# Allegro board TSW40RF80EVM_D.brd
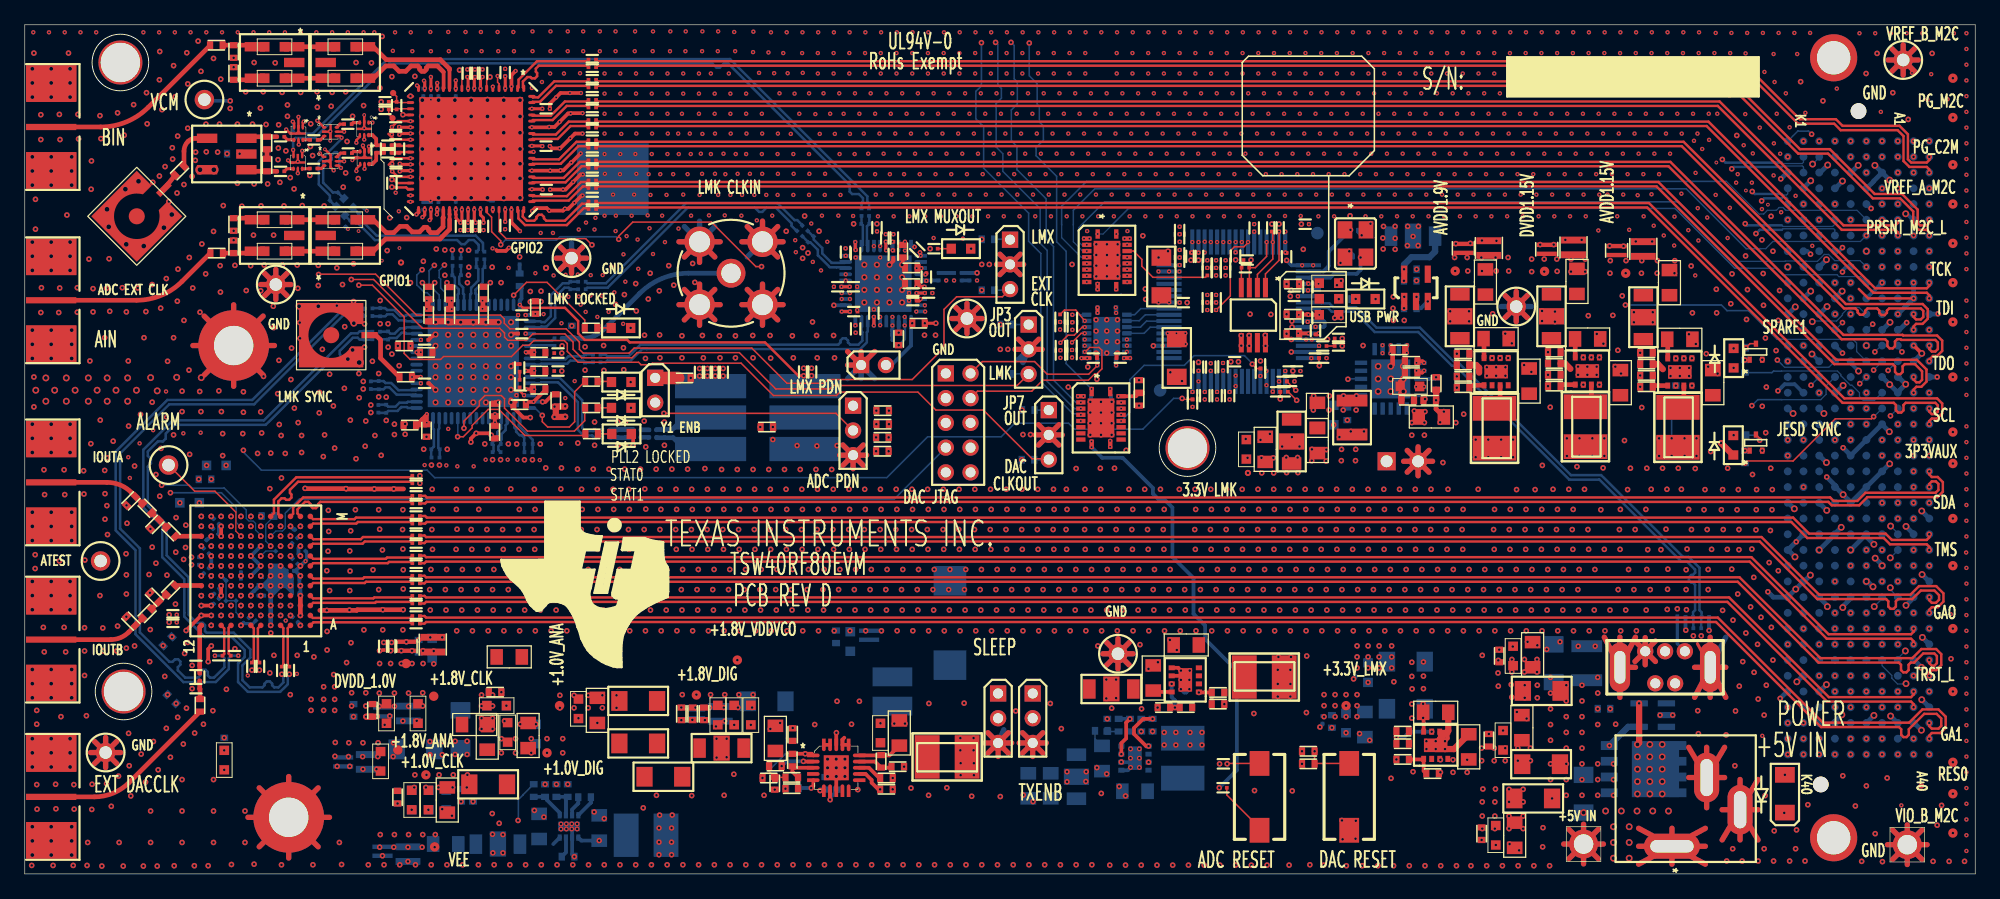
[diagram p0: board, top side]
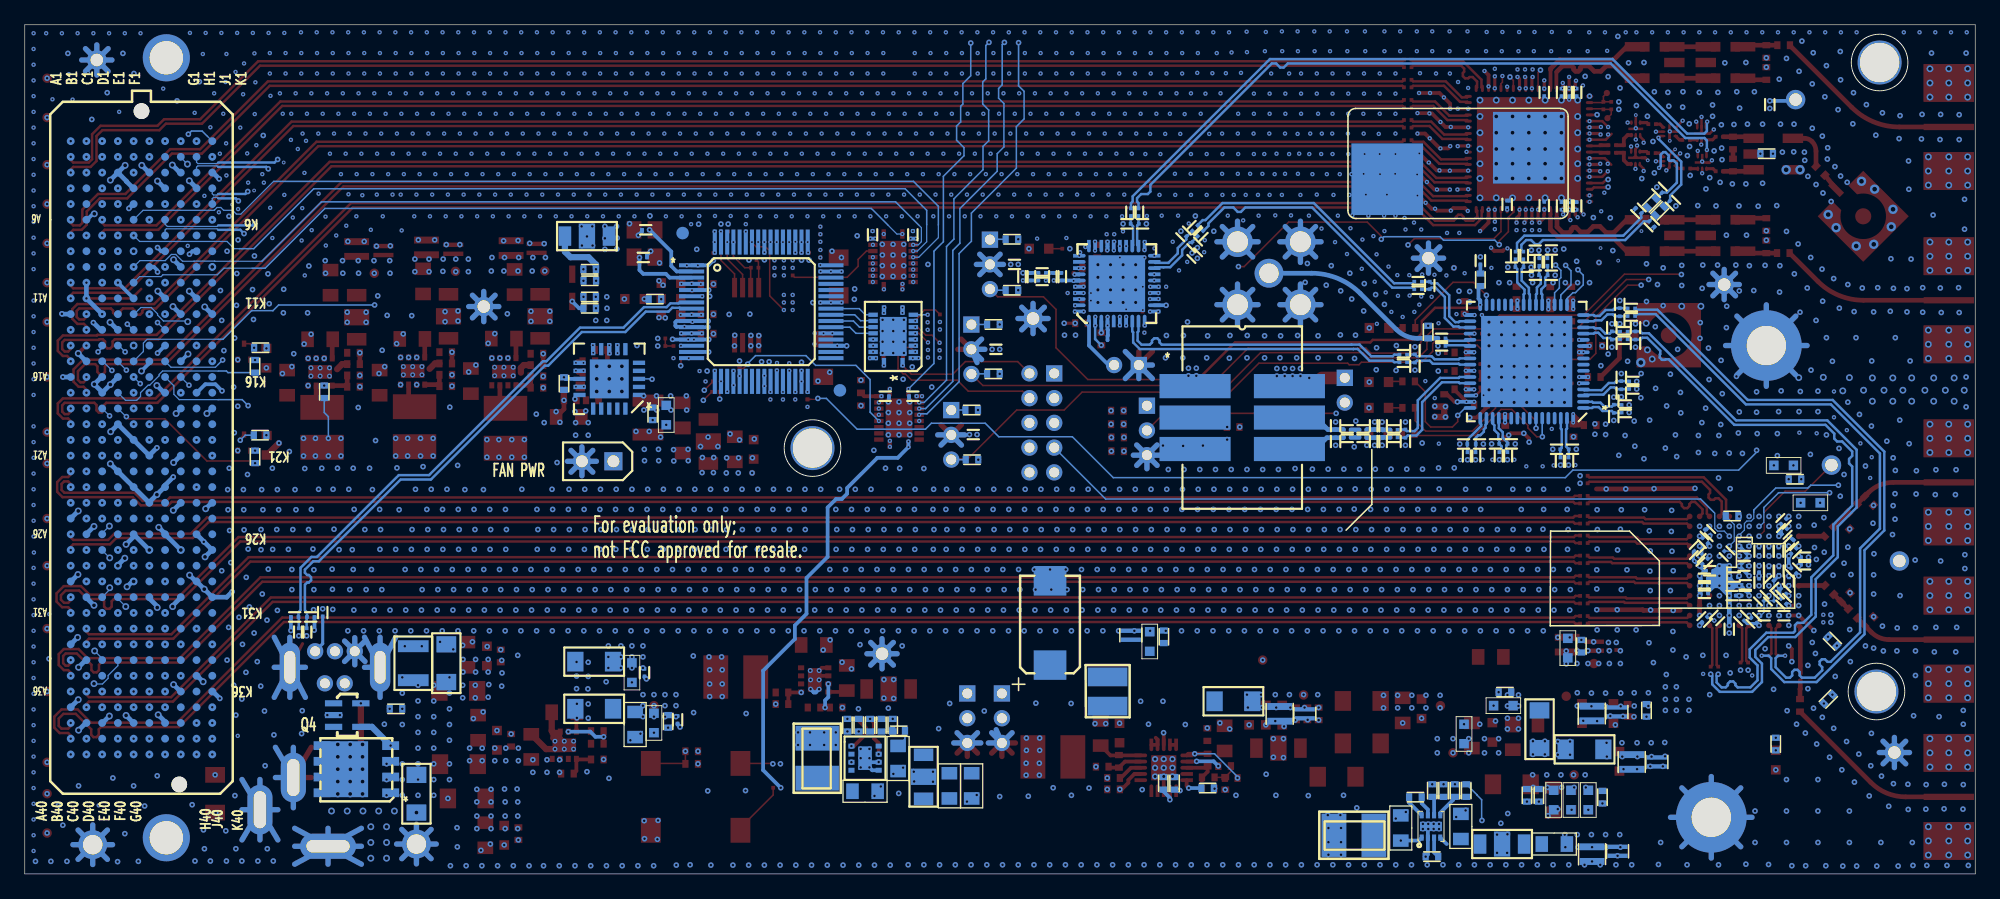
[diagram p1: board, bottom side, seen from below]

Outline 157.48 x 68.58 mm; copper layers: TOP, L2_GND, L3_PWR_SIG, L4_SIG, L5_GND, L6_SIG, L7_GND, L8_SIG, L9_GND, L10_PWR_SIG, L11_GND, BOTTOM. Coordinates in mm from the lower left corner of the outline.
Outline path: 0,68.58 0,0 157.48,0 157.48,68.58 0,68.58

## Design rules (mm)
net group ADC_SYNC: nets ADC_SYNC_N ADC_SYNC_P
net group ADC_SYSREF: nets ADC_SYSREFN ADC_SYSREFP
net group CAR_SYSREF: nets CAR_SYSREFM CAR_SYSREFP
net group CLK_LAO: nets CLK_LAO_0M CLK_LAO_0P
net group CLKIN0: nets CLKIN0_N CLKIN0_P
net group DA0: nets DA0N DA0P
net group DAC_ALT_SYNC: nets DAC_ALT_SYNC_N DAC_ALT_SYNC_P
net group DAC_CLK: nets LMK_DAC_CLKN LMK_DAC_CLKP
net group DAC_CLKOUT: nets DAC_CLKOUTN DAC_CLKOUTP
net group DAC_SYNC: nets DAC_SYNC_N DAC_SYNC_P
net group DCLKOUT2: nets DCLKOUT2N DCLKOUT2P
net group DCLKOUT4: nets DCLKOUT4N DCLKOUT4P
net group DIFFPAIR9: nets GTXCLKM GTXCLKP
net group DIFFPAIR12: nets FPGA_CLK1N FPGA_CLK1P
net group DIFFPAIR13: nets FPGA_CLK1_N FPGA_CLK1_P
net group DIFFPAIR14: nets FPGA_CLK2N FPGA_CLK2P
net group DIFFPAIR15: nets FPGA_CLK2_N FPGA_CLK2_P
net group DP0_C2M: nets DP0_C2M_N DP0_C2M_P
net group DP1: nets DM DP
net group DP1_C2M: nets DP1_C2M_N DP1_C2M_P
net group DP2: nets CLKLA_0M CLKLA_0P
net group DP2_C2M: nets DP2_C2M_N DP2_C2M_P
net group DP2_M2C: nets DB2N DB2P
net group DP3: nets CAR_SYSREF_M CAR_SYSREF_P
net group DP3_C2M: nets DP3_C2M_N DP3_C2M_P
net group DP3_M2C: nets DB0N DB0P
net group DP4: nets DACCLK_N DACCLK_P
net group DP4_C2M: nets DP4_C2M_N DP4_C2M_P
net group DP4_M2C: nets DA1N DA1P
net group DP5: nets N20165749 N20165751
net group DP5_C2M: nets DP5_C2M_N DP5_C2M_P
net group DP5_M2C: nets DA3N DA3P
net group DP6_C2M: nets DP6_C2M_N DP6_C2M_P
net group DP6_M2C: nets DA2N DA2P
net group DP7: nets OSCI OSCO
net group DP7_C2M: nets DP7_C2M_N DP7_C2M_P
net group DP8: nets AINM AINP
net group DP8_M2C: nets DB1N DB1P
net group DP9: nets BINM BINP
net group DP9_M2C: nets DB3N DB3P
net group DP10: nets ADC_CLKINM ADC_CLKINP
net group DP11: nets TXA0_M TXA0_P
net group DP12: nets TXA1_M TXA1_P
net group DP13: nets TXA2_M TXA2_P
net group DP14: nets TXA3_M TXA3_P
net group DP15: nets TXB0_M TXB0_P
net group DP16: nets TXB1_M TXB1_P
net group DP17: nets TXB2_M TXB2_P
net group DP18: nets TXB3_M TXB3_P
net group DP19: nets LMX_OSCM LMX_OSCP
net group DP20: nets CLKIN1N CLKIN1P
net group DP21: nets N20076866 N20076868
net group GTX_CLK: nets GTX_CLKM GTX_CLKP
net group LMK_ADC_CLK: nets LMK_ADC_CLKN LMK_ADC_CLKP
net group LMK_DAC_SYSREF: nets LMK_DAC_SYSREFN LMK_DAC_SYSREFP
net group LMX_CLKA: nets LMX_CLKAN LMX_CLKAP
net group LMX_CLKB: nets LMX_CLKBN LMX_CLKBP
net group OSCIN: nets OSCINN OSCINP
net group OSCOUT: nets OSCOUTN OSCOUTP
net group RX0: nets RX0N RX0P
net group RX1: nets RX1N RX1P
net group RX2: nets RX2N RX2P
net group RX3: nets RX3N RX3P
net group RX4: nets RX4N RX4P
net group RX5: nets RX5N RX5P
net group RX6: nets RX6N RX6P
net group RX7: nets RX7N RX7P
net group SDCLKOUT3: nets SDCLKOUT3N SDCLKOUT3P
net group SDCLKOUT5: nets SDCLKOUT5N SDCLKOUT5P
net group SYSREF-: nets SYSREF-N SYSREF-P
net group USB_M: nets USB_DM USB_DP
net group Y2: nets Y2_N Y2_P

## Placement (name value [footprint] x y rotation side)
C1  0.01uF  [0402]  14.15 13.61 90 top
C7  .1uF  [0201]  18.34 16.76 270 top
C9  .1uF  [0201]  18.95 16.76 270 top
C10  .1uF  [0201]  31.6 20.83 180 top
C11  .1uF  [0201]  31.6 20.22 180 top
C12  .1uF  [0201]  31.6 21.84 180 top
C13  .1uF  [0201]  31.6 22.45 180 top
C14  .1uF  [0201]  31.6 23.47 180 top
C15  .1uF  [0201]  31.6 24.08 180 top
C16  .1uF  [0201]  31.6 25.7 180 top
C17  .1uF  [0201]  31.6 25.1 180 top
C18  .1uF  [0201]  31.6 31.55 180 top
C19  .1uF  [0201]  31.6 32.16 180 top
C20  .1uF  [0201]  31.6 29.92 180 top
C21  .1uF  [0201]  31.6 28.91 180 top
C22  .1uF  [0201]  31.6 30.53 180 top
C23  .1uF  [0201]  31.6 28.3 180 top
C24  .1uF  [0201]  31.6 27.33 180 top
C25  .1uF  [0201]  31.6 26.72 180 top
C26  5600pF  [0402]  11.81 27.63 135 top
C27  5600pF  [0402]  11.79 22.94 225 top
C28  .001uF  [0402]  103.63 9.91 180 top
C29  .1uF  [0201]  11.96 20.32 180 top
C30  10uF  [0603]  32.89 18.24 90 bottom
C31  1uF  [0402]  31.8 18.39 270 bottom
C32  .1uF  [0201]  21.87 23.27 0 bottom
C33  .1uF  [0201]  19.46 23.98 180 bottom
C34  .1uF  [0201]  19.63 22.48 180 bottom
C35  .1uF  [0201]  18.57 23.34 180 bottom
C36  .1uF  [0201]  19.86 19.76 270 bottom
C37  .1uF  [0201]  29.62 18.39 90 top
C38  .1uF  [0201]  21.44 24.49 0 bottom
C39  .1uF  [0201]  21.87 23.88 0 bottom
C40  .1uF  [0201]  18.57 22.48 0 bottom
C41  .1uF  [0201]  21.87 22.66 0 bottom
C42  .1uF  [0201]  28.98 18.39 90 top
C43  10uF  [0603]  41.27 11.3 90 bottom
C44  1uF  [0201]  18.67 24.87 0 bottom
C45  .1uF  [0201]  18.67 25.68 0 bottom
C46  .1uF  [0201]  18.64 26.47 180 bottom
C47  10uF  [0603]  38.1 13.59 0 top
C48  1uF  [0402]  37.97 14.68 180 top
C49  .1uF  [0201]  21.79 26.92 45 bottom
C50  .1uF  [0201]  21.82 25.25 315 bottom
C51  10uF  [0603]  31.24 5.97 270 top
C52  1uF  [0402]  35.23 6.35 90 bottom
C53  .1uF  [0201]  16.66 26.06 90 bottom
C54  .1uF  [0201]  16.66 24.46 270 bottom
C55  10uF  [0603]  32.64 5.97 270 bottom
C56  1uF  [0402]  36.2 6.35 90 bottom
C57  .1uF  [0201]  17.27 22.28 225 bottom
C58  .1uF  [0201]  17.45 23.55 90 bottom
C59  10uF  [0603]  38.1 13.59 0 bottom
C60  1uF  [0402]  37.97 14.68 180 bottom
C61  .1uF  [0201]  17.45 26.06 90 bottom
C62  .1uF  [0201]  17.45 24.66 270 bottom
C63  10uF  [0603]  31.24 5.97 270 bottom
C64  1uF  [0402]  30.1 6.2 90 top
C65  .1uF  [0201]  15.88 26.06 90 bottom
C66  .1uF  [0201]  15.85 24.46 270 bottom
C67  10uF  [0603]  15.47 32.99 180 bottom
C68  1uF  [0402]  14.55 31.88 0 bottom
C69  .1uF  [0201]  14.88 26.75 135 bottom
C70  .1uF  [0201]  15.04 23.65 270 bottom
C71  10uF  [0603]  16.1 9.19 270 top
C72  1uF  [0402]  16.1 10.49 270 bottom
C73  .1uF  [0201]  14.66 24.49 225 bottom
C74  .1uF  [0201]  14.66 26.09 135 bottom
C75  10uF  [0603]  28.73 9.09 270 top
C76  1uF  [0402]  11.86 14.12 315 bottom
C77  .1uF  [0201]  13.77 25.58 180 bottom
C78  .1uF  [0201]  13.77 24.97 180 bottom
C79  10uF  [0603]  29.21 12.95 270 top
C80  1uF  [0402]  28.07 13.21 90 top
C81  .1uF  [0201]  15.44 20.85 180 bottom
C82  .1uF  [0201]  17.04 20.85 0 bottom
C83  10uF  [0603]  66.65 18.77 90 bottom
C84  1uF  [0402]  65.51 19.15 270 bottom
C85  .1uF  [0201]  16.46 22.28 225 bottom
C86  .1uF  [0201]  16.48 23.47 135 bottom
C87  1uF  [0402]  30.1 6.2 90 bottom
C88  .1uF  [0201]  18.87 20.68 225 bottom
C89  10uF  [0603]  58.62 12.83 270 top
C90  1uF  [0402]  54.84 12.93 90 top
C91  .1uF  [0201]  21.84 20.55 315 bottom
C92  .1uF  [0201]  20.85 20.68 315 bottom
C93  10uF  [0603]  57.28 12.83 270 top
C94  1uF  [0402]  53.01 12.93 90 top
C95  10uF  [0603]  34.04 5.97 270 bottom
C96  .1uF  [0201]  20.04 25.86 45 bottom
C97  10uF  [0603]  55.96 12.83 270 top
C98  1uF  [0402]  53.92 12.93 90 top
C99  .1uF  [0201]  22.45 25.48 315 bottom
C100  .1uF  [0201]  22.45 26.29 315 bottom
C101  10uF  [0603]  31.75 12.95 270 top
C102  1uF  [0402]  26.54 13.21 90 bottom
C103  .1uF  [0201]  17.88 20.47 225 bottom
C104  10uF  [0603]  13.31 29.97 180 bottom
C105  1uF  [0402]  11.53 18.8 45 bottom
C106  .1uF  [0201]  15.42 27.66 135 bottom
C107  .1uF  [0201]  15.47 28.47 135 bottom
C108  .1uF  [0201]  15.49 22.83 225 bottom
C109  .1uF  [0201]  15.47 22.02 225 bottom
C110  .1uF  [0201]  45.82 58.65 0 top
C111  .1uF  [0201]  45.82 59.26 0 top
C112  .1uF  [0201]  36.4 52.3 270 top
C113  .1uF  [0201]  35.18 52.3 270 top
C114  .1uF  [0201]  34.8 53.98 90 bottom
C115  .1uF  [0201]  33.4 53.95 90 bottom
C116  .1uF  [0201]  32.18 53.95 90 bottom
C117  .1uF  [0201]  29.97 57.35 180 top
C118  .1uF  [0201]  29.95 59.72 180 top
C119  .1uF  [0201]  32.18 63.12 270 bottom
C120  .1uF  [0201]  33.4 63.12 270 bottom
C121  .1uF  [0201]  34.8 63.12 270 bottom
C122  .1uF  [0201]  36.35 64.67 90 top
C123  .1uF  [0201]  45.82 57.02 0 top
C124  .1uF  [0201]  45.82 57.63 0 top
C125  .1uF  [0201]  45.82 55.4 0 top
C126  .1uF  [0201]  45.82 56.01 0 top
C127  .1uF  [0201]  45.82 53.7 0 top
C128  .1uF  [0201]  42.09 61.8 0 top
C129  .1uF  [0201]  42.09 58.78 0 top
C130  .1uF  [0201]  42.11 55.27 0 top
C131  .1uF  [0201]  38.79 52.37 270 top
C132  .1uF  [0201]  37.03 52.3 270 top
C133  .1uF  [0201]  36.96 64.67 90 top
C134  .1uF  [0201]  38.79 64.72 90 top
C135  .1uF  [0201]  45.82 54.31 0 top
C136  .1uF  [0201]  45.82 60.88 0 top
C137  .1uF  [0201]  45.82 60.27 0 top
C138  .1uF  [0201]  45.82 62.51 0 top
C139  .1uF  [0201]  77.57 49.23 0 bottom
C140  .1uF  [0201]  45.82 61.9 0 top
C141  .1uF  [0201]  45.82 64.14 0 top
C142  .1uF  [0201]  35.79 52.3 270 top
C143  .1uF  [0201]  32.79 53.95 90 bottom
C144  .01uF  [0201]  29.97 56.74 180 top
C145  .01uF  [0201]  29.95 60.33 180 top
C146  .1uF  [0201]  32.79 63.12 270 bottom
C147  .1uF  [0201]  35.74 64.67 90 top
C148  .1uF  [0201]  45.82 63.53 0 top
C149  .1uF  [0201]  45.82 65.76 0 top
C150  .1uF  [0201]  45.82 65.15 0 top
C153  .01uF  [0402]  12.5 56.79 45 top
C154  .1uF  [0402]  16.84 58.17 180 bottom
C157  .1uF  [0201]  16.59 62.13 270 bottom
C158  .1uF  [0603]  25.88 52.83 0 top
C159  .1uF  [0402]  16.87 52.45 90 top
C160  .1uF  [0402]  15.49 50.14 0 top
C161  .1uF  [0402]  16.87 50.65 270 top
C162  .1uF  [0603]  25.88 50.29 0 top
C163  .1uF  [0603]  25.88 66.8 0 top
C164  .1uF  [0402]  15.47 66.93 0 top
C165  .1uF  [0402]  16.87 66.42 90 top
C166  .1uF  [0402]  16.87 64.64 270 top
C167  .1uF  [0603]  25.88 64.26 0 top
C168  100pF  [0201]  68.81 52.2 270 top
C170  10pF  [0201]  68.17 53.44 90 bottom
C171  10pF  [0201]  67.56 53.44 90 bottom
C172  .1uF  [0201]  68.55 45.29 90 top
C173  .1uF  [0201]  65.63 47.42 180 top
C174  1uF  [0201]  66.9 47.42 180 top
C176  .1uF  [0201]  66.93 45.42 0 top
C177  .1uF  [0201]  67.08 44.02 90 top
C178  100pF  [0201]  63.02 49.93 225 bottom
C179  .1uF  [0201]  67.08 50.09 270 top
C180  .1uF  [0201]  69.52 51.36 270 top
C181  10pF  [0201]  62.56 51.72 135 bottom
C182  .1uF  [0201]  70.13 50.04 270 top
C183  1uF  [0201]  70.13 51.36 270 top
C184  10pF  [0201]  62.99 52.15 135 bottom
C185  .1uF  [0201]  72.97 46.91 0 top
C186  10uF  [0402]  70.89 50.29 90 top
C187  1uF  [0201]  71.7 46.91 0 top
C188  10uF  [0402]  71.58 47.68 0 top
C189  1uF  [0201]  71.7 46.3 0 top
C190  10uF  [0402]  70.56 43.21 90 top
C191  10uF  [0402]  71.58 48.95 0 top
C192  560pF  [0201]  76.89 48.23 270 bottom
C193  .047uF  [0201]  76.28 48.23 270 bottom
C194  6800pF  [0201]  74.4 48.23 270 bottom
C195  6800pF  [0201]  72.8 48.21 90 top
C196  0.1uF  [0201]  27.76 45.06 180 bottom
C197  0.1uF  [0201]  27.76 45.67 180 bottom
C198  .68uF  [0402]  39.95 47.98 90 bottom
C199  0.1uF  [0201]  28.24 37.26 180 bottom
C200  0.1uF  [0201]  62.89 40.54 90 top
C201  0.1uF  [0201]  28.24 37.87 180 bottom
C202  3900pF  [0201]  39.95 39.6 90 top
C203  47pF  [0201]  40.01 38.66 180 top
C204  0.1uF  [0201]  43.08 43.26 180 bottom
C206  0.1uF  [0201]  43.08 42.65 180 bottom
C207  10pF  [0201]  36.49 49.95 90 bottom
C208  10pF  [0201]  37.11 49.95 90 bottom
C216  0.1uF  [0201]  38.42 33.76 270 bottom
C217  0.1uF  [0201]  37.77 33.76 270 bottom
C218  0.1uF  [0201]  54.48 40.51 270 top
C219  100pF  [0201]  55.12 40.51 270 top
C220  0.1uF  [0201]  49.43 35.86 180 bottom
C221  .1uF  [0201]  46.95 35.86 180 bottom
C222  2200pF  [0201]  55.75 40.51 270 top
C223  0.1uF  [0201]  46.01 36.19 270 bottom
C224  0.1uF  [0201]  40.99 33.75 270 bottom
C225  10pF  [0201]  56.39 40.51 270 top
C226  0.1uF  [0201]  40.34 33.75 270 bottom
C227  0.1uF  [0201]  49.43 35.25 180 bottom
C228  0.1uF  [0201]  46.95 35.25 180 bottom
C229  12pF  [0201]  46.01 34.92 90 bottom
C230  .1uF  [0201]  46.18 41.94 0 bottom
C231  .1uF  [0201]  46.18 41.33 0 bottom
C232  1uF  [0402]  32.41 42.11 180 top
C233  .1uF  [0201]  40.13 45.13 0 top
C234  0.01uF  [0201]  40.13 43.64 0 top
C235  1uF  [0402]  32.61 45.13 90 top
C236  1uF  [0402]  34.32 45.11 90 top
C237  1uF  [0402]  37.03 45.13 90 top
C238  1uF  [0402]  39.95 37.9 0 top
C239  .1uF  [0201]  43.05 40.61 180 top
C240  0.01uF  [0201]  43.05 42.06 180 top
C241  .1uF  [0201]  32.28 43.13 0 top
C242  10uF  [0402]  30.63 42.65 180 top
C243  1uF  [0402]  37.95 37.47 270 top
C244  1uF  [0402]  32.44 35.81 90 top
C245  .1uF  [0201]  94.76 40.93 270 top
C246  .1uF  [0201]  94.16 49.88 90 top
C247  .1uF  [0201]  103.58 44.9 270 top
C248  4.7uF  [0402]  102.38 45.2 180 top
C249  .1uF  [0201]  93.55 46.14 180 top
C250  .1uF  [0201]  101.88 49.85 90 top
C251  .1uF  [0201]  94.76 49.88 90 top
C252  10uF  [0402]  111.87 46.6 0 bottom
C253  .1uF  [0201]  104.21 43.88 270 top
C254  1uF  [0402]  111.86 47.9 0 bottom
C255  .1uF  [0201]  97.76 49.9 90 top
C256  10uF  [0402]  111.87 48.83 0 bottom
C257  .1uF  [0201]  103.6 47.41 270 top
C258  4.7uF  [0402]  102.38 47.64 180 top
C259  100uF  [1206]  91.77 48.25 90 top
C260  .1uF  [0201]  88.01 38.58 0 bottom
C261  .1uF  [0201]  85.78 38.58 0 bottom
C262  10uF  [0402]  102.38 43.63 180 top
C263  100uF  [1206]  93.01 41.67 270 top
C264  .1uF  [0201]  88.45 41.66 180 top
C265  .1uF  [0201]  86.27 41.66 180 top
C266  22pF  [0201]  134.39 20.75 180 bottom
C267  22pF  [0201]  135.69 20.75 0 bottom
C268  .1uF  [0201]  97.69 41.37 0 top
C269  27pF  [0201]  107.34 52.02 0 bottom
C270  27pF  [0201]  107.55 49.79 180 bottom
C273  47uF  [1210]  126.11 17.02 90 bottom
C274  22uF  [1206]  123.44 17.02 270 bottom
C275  10uF  [0805]  120.29 3.12 270 top
C276  1.0uF  [0603]  118.77 3.12 270 top
C277  .1uF  [0402]  117.63 3.25 90 top
C278  10uF  [0508]  30.94 1.6 270 bottom
C279  47uF  [0805]  41.53 3.84 90 bottom
C280  1uF  [0306]  28.88 1.83 270 bottom
C281  10uF  [0805]  46.38 3.71 90 bottom
C282  1uF  [0402]  45.2 6.2 0 bottom
C283  4.7uF  [0402]  43.87 1.4 0 bottom
C285  10uF  [0805]  93.78 18.49 180 top
C288  10uF  [0508]  32.94 18.52 90 top
C289  1uF  [0306]  30.78 18.39 90 top
C290  22uF  [0805]  91.11 15.82 270 top
C294  22uF  [0805]  86.97 9.32 90 bottom
C295  10uF  [0805]  81.03 7.11 270 bottom
C297  10uF  [0508]  30.96 12.95 270 bottom
C298  1uF  [0306]  28.93 13.08 270 bottom
C299  10uF  [0805]  89.64 6.68 180 bottom
C300  10uF  [0508]  56.16 12.93 270 bottom
C301  1uF  [0306]  54.13 12.93 270 bottom
C302  10uF  [0508]  27.74 9.04 270 bottom
C303  1uF  [0306]  25.7 9.04 270 bottom
C308  10uF  [0805]  34.11 5.97 270 top
C309  1.0uF  [0603]  32.59 5.97 270 top
C313  .1uF  [0402]  62 11.25 270 top
C314  10uF  [0805]  40.64 11.18 90 top
C315  47uF  [0805]  60.6 10.95 90 top
C316  1.0uF  [0603]  38.99 11.43 90 top
C317  0.01uF  [0402]  61.98 9.19 90 top
C318  47uF  [0805]  70.61 11.38 90 top
C320  1.0uF  [0603]  69.09 11.38 90 top
C324  10uF  [0805]  46.23 13.21 270 top
C325  1.0uF  [0603]  44.7 13.34 270 top
C326  0.01uF  [0402]  69.57 7.75 180 top
C327  1.0uF  [0402]  69.57 6.83 180 top
C340  10uF  [0805]  113.56 36.91 0 top
C341  .1uF  [0402]  113.44 38.25 180 top
C342  0.01uF  [0402]  111.66 38.25 0 top
C343  .1uF  [0402]  106.78 37.16 270 bottom
C344  1.0uF  [0603]  105.69 37.06 270 bottom
C345  47uF  [1210]  107.16 36.86 270 top
C346  10uF  [0805]  100.15 34.29 90 top
C347  1.0uF  [0603]  98.63 34.29 90 top
C348  1.0uF  [0603]  111.84 39.37 180 top
C353  33uF  [0805]  108.2 12.06 270 bottom
C354  10uF  [0603]  106.68 12.19 270 bottom
C355  .1uF  [0402]  105.54 12.32 270 bottom
C356  .01uF  [0201]  104.78 12.45 270 bottom
C358  10uF  [0603]  108.46 16.26 270 bottom
C359  .01uF  [0201]  107.44 16.26 270 bottom
C360  .1uF  [0201]  15.66 17.62 180 top
C361  .1uF  [0201]  16.94 17.63 0 top
C362  10uF  [0508]  118.21 50.55 90 top
C364  1uF  [0306]  116.15 50.52 90 top
C365  10uF  [0805]  121.46 39.8 90 top
C366  22uF  [0805]  118.8 43.23 180 top
C367  10uF  [0805]  136.3 39.67 90 top
C376  22uF  [0805]  133.63 43.18 180 top
C377  10uF  [0508]  125.04 50.6 90 top
C378  1uF  [0306]  122.89 50.44 90 top
C379  10uF  [0805]  128.83 39.67 90 top
C380  22uF  [0805]  126.19 43.21 180 top
C381  10uF  [0508]  130.68 50.47 90 top
C382  1uF  [0306]  128.52 50.34 90 top
C383  .01uF  [0201]  44.98 47.83 180 bottom
C384  .01uF  [0201]  44.98 47.22 180 bottom
C423  .1uF  [0201]  79.07 42.37 0 bottom
C424  .1uF  [0201]  80.9 35.48 0 bottom
C425  10uF  [0805]  116.59 10.26 90 top
C426  22uF  [0805]  113.92 13.06 180 top
C427  10pF  [0201]  29.31 58.85 0 top
C428  10pF  [0201]  29.31 58.24 0 top
C429  10pF  [0201]  20.65 59.54 0 top
C430  10pF  [0201]  20.65 56.74 0 top
C431  10pF  [0201]  23.34 59.28 0 top
C432  10pF  [0201]  23.32 56.97 0 top
C433  10pF  [0201]  26.09 60.55 0 top
C434  10pF  [0201]  26.11 58.22 0 top
C435  1.0uF  [0603]  120.17 17.6 90 top
C436  .1uF  [0402]  119.05 17.6 270 top
C437  10uF  [0805]  121.74 17.7 90 top
C438  .1uF  [0201]  89.03 51.61 90 bottom
C439  .1uF  [0201]  85.78 51.61 270 bottom
C440  1.0uF  [0603]  119.35 10.79 90 top
C441  .1uF  [0402]  118.21 10.79 270 top
C442  10uF  [0805]  120.88 11.81 90 top
C443  1uF  [0306]  68.17 19.28 90 bottom
C444  470uF  [7343]  74.7 20.27 90 bottom
C445  TBD  [0201]  26.12 52.48 45 bottom
C446  TBD  [0201]  27.19 53.56 225 bottom
C447  TBD  [0201]  24.42 54.17 45 bottom
C448  TBD  [0201]  25.49 55.25 225 bottom
D1  LED GREEN  [LED_0603]  75.59 50.5 0 top
D2  LED GREEN  [LED_0603]  48.16 37.64 0 top
D3  LED GREEN  [LED_0603]  48.18 35.53 0 top
D4  LED GREEN  [LED_0603]  48.13 44.09 0 top
D5  LED GREEN  [LED_0603]  48.16 39.73 0 top
D6  LED GREEN  [LED_0603]  137.95 34.62 90 top
D7  LED GREEN  [LED_0603]  137.97 41.66 90 top
D9  LED GREEN  [LED_0603]  108.24 46.43 0 top
D10  LED GREEN  [LED_1206]  142.11 6.48 270 top
F1  FUSE 2.0A 63V FAST  [1206]  125.86 6.48 90 bottom
FB1  120  [0402]  53.26 40.06 0 top
FB2  120  [0402]  41.22 45.74 270 top
FB3  120  [0402]  34.32 46.89 270 top
FB4  120  [0402]  37.03 46.91 270 top
FB5  120  [0402]  32.61 46.91 270 top
FB6  120  [0402]  42.88 38.23 90 top
FB7  120  [0402]  41.53 42.11 180 top
FB8  120  [0402]  41.53 40.61 180 top
FB9  120  [0402]  41.53 39.14 180 top
FB10  120  [0402]  37.95 35.69 90 top
FB11  120  [0402]  31.09 36.25 0 top
FB12  60 OHM @ 100MHz  [0603]  105.31 45.15 180 top
FB13  27uF  [1206_BEAD_NFM31P]  112.09 51.51 180 bottom
FB14  68 OHM @ 100MHz  [0603]  105.31 47.72 180 top
FB15  68 OHM @ 100MHz  [0603]  105.31 46.45 180 top
FB16  120 @100MHz  [1206]  121.79 6.1 0 top
FB17  27uF  [1206_BEAD_NFM31P]  38.2 2.41 180 bottom
FB18  27uF  [1206_BEAD_NFM31P]  87.73 14.94 180 top
FB20  27uF  [1206_BEAD_NFM31P]  84.91 7.85 270 bottom
FB21  120 OHM @ 100MHz  [1206]  50.11 3.1 180 bottom
FB22  120 OHM @ 100MHz  [1206]  100.1 15.95 180 top
FB23  120 OHM @ 100MHz  [1206]  93.55 9.32 270 bottom
FB24  120 OHM @ 100MHz  [1206]  74.47 9.42 0 top
FB25  120 OHM @ 100MHz  [1206]  118.85 35.99 90 top
FB26  120 OHM @ 100MHz  [1206]  133.53 36.07 90 top
FB27  120 OHM @ 100MHz  [1206]  126.09 36.12 90 top
FB37  27uF  [1206_BEAD_NFM31P]  102.29 34.92 270 top
FB38  120 OHM @ 100MHz  [1206]  111.51 13.34 180 bottom
FB39  120 OHM @ 100MHz  [1206]  111.51 17.14 180 bottom
FB40  27uF  [1206_BEAD_NFM31P]  123.27 45.03 90 top
FB41  27uF  [1206_BEAD_NFM31P]  130.68 44.96 90 top
FB42  27uF  [1206_BEAD_NFM31P]  115.87 45.03 90 top
FB44  120 @100MHz  [1206]  122.48 14.78 0 top
FB45  120 @100MHz  [1206]  122.43 8.86 0 top
FB47  120 OHM @ 100MHz  [1206]  35.18 11.68 90 bottom
FB48  120 OHM @ 100MHz  [1206]  59.89 13.94 180 bottom
FB49  120 OHM @ 100MHz  [1206]  31.55 10.06 180 bottom
FB50  120 OHM @ 100MHz  [1206]  37.41 7.24 180 top
FB51  120 OHM @ 100MHz  [1206]  49.53 10.54 180 top
FB52  120 OHM @ 100MHz  [1206]  49.53 13.97 180 top
FB53  27uF  [1206_BEAD_NFM31P]  56.26 10.16 180 top
HS1  HEAT SINK, DAC38RF8x, RED  [HEATSINK_SVT_10-1003850]  20.04 24.26 0 top
HS2  Copper Heatsink, .7 x .35 with FAN assembly  [HEATSINK_350X700]  41.76 57.38 180 bottom
J1  SMA, JACK, END LAUNCH  [SMA_SMEL_DUAL_PSF-S01_250X215]  0.1 6.22 90 top
J3  SMA, JACK, END LAUNCH  [SMA_SMEL_DUAL_PSF-S01_250X215]  0.1 31.62 90 top
J4  SMA, JACK, END LAUNCH  [SMA_SMEL_DUAL_PSF-S01_250X215]  0.1 18.92 90 top
J5  HDR 2X5  [HDR_THVT_2X5_79_M]  75.36 36.42 0 top
J8  SMP CONN  [SMP_B120]  9.04 53.11 135 top
J9  SMA, JACK, END LAUNCH  [SMA_SMEL_DUAL_PSF-S01_250X215]  0.1 46.33 90 top
J10  SMA, JACK, END LAUNCH  [SMA_SMEL_DUAL_PSF-S01_250X215]  0.1 60.33 90 top
J12  SMA_THVT_REC  [SMA_THVT_312X312]  57.02 48.51 0 top
J13  SMP CONN  [SMP_B120]  24.74 43.51 90 top
J14  CON_SMVT_40x10_SEAM  [CON_SMVT_40X10_SEAM_MTG]  148.06 34.42 90 bottom
J15  MINI B USB 2.0 OTG Receptacle, Vertical  [CON_THVT_USBMINI_AB_F]  132.44 16.69 180 top
J17  PJ-006A  [JACK_THVT_3_520X343X421]  132.99 2.24 270 top
J38  HEADER 2POS, FAN POWER  [HDR_THVT_1X2_100_M]  109.96 33.32 270 bottom
JP1  HDR 1x3 2mm  [HDR_THVT_1X3_79_M]  78.59 12.57 0 top
JP2  HDR 1x3 2mm  [HDR_THVT_1X3_79_M]  81.38 12.57 0 top
JP3  HDR 1x3 2mm  [HDR_THVT_1X3_79_M]  79.55 49.23 0 top
JP4  HDR 1x3 2mm  [HDR_THVT_1X3_79_M]  66.88 35.81 0 top
JP5  HDR 1x2 2mm  [HDR_THVT_1X2_79_M]  68.53 41.1 90 top
JP6  HDR 1x2 2mm  [HDR_THVT_1X2_79_M]  50.9 39.07 0 top
JP7  HDR 1x3 2mm  [HDR_THVT_1X3_79_M]  81.05 42.37 0 top
JP8  HDR 1x3 2mm  [HDR_THVT_1X3_79_M]  82.68 35.46 0 top
L10  1uH  [IND_SM_142X189]  118.67 35.99 90 top
L11  1uH  [IND_SM_142X189]  133.48 36.07 90 top
L12  1uH  [IND_SM_142X189]  126.01 36.12 90 top
L13  1uH  [IND_SM_142X189]  93.5 9.35 270 bottom
L14  1uH  [IND_SM_142X189]  74.47 9.45 0 top
L15  1uH  [IND_SM_142X189]  50.16 3.12 180 bottom
L16  1uH  [IND_SM_142X189]  100.08 15.9 180 top
L17  100uH  [IND_SM_110X138]  70.05 14.71 270 bottom
L18  0 ohm  [0402]  25.48 53.54 135 bottom
L19  0 ohm  [0402]  26.12 54.19 135 bottom
MT1  STANDOFF,  4-40, 3/16 Rd x 1 3/16 Length, ALUM  [MFG125_PLATED]  7.98 14.73 0 top
MT2  STANDOFF,  4-40, 3/16 Rd x 1 3/16 Length, ALUM  [MFG125_PLATED]  7.72 65.53 0 top
MT3  STANDOFF,  4-40, 3/16 Rd x 1 3/16 Length, ALUM  [MFG125_PLATED]  93.88 34.39 0 top
NOREF  -  []  32.87 54.84 0 top
NOREF#2  -  []  116.94 5.84 89.9 top
NOREF#3  -  []  94.92 3.91 0 top
NOREF#4  -  []  32.87 56.74 0 top
NOREF#5  -  []  50.01 79.6 90 top
NOREF#6  -  []  49.38 79.6 90 top
NOREF#7  -  []  91.54 24.26 0 top
NOREF#8  -  []  27.41 33.53 0 top
NOREF#9  -  []  473.3 162.18 0 top
NOREF#10  -  []  35.79 3.94 90 top
NOREF#11  -  []  82.65 4.57 0 top
NOREF#12  -  []  -116.97 325.27 0 top
NOREF#13  -  []  38.58 79.6 90 top
NOREF#14  -  []  395.25 73.96 0 top
NOREF#15  -  []  38.05 60.02 0 top
NOREF#16  -  []  220.98 11.43 0 top
NOREF#17  -  []  5.08 0 90 top
NOREF#18  -  []  58.17 61.11 0 top
NOREF#19  -  []  44.3 58.65 0 top
NOREF#20  -  []  36.64 28.06 0 top
NOREF#21  -  []  59.54 87.86 0 top
NOREF#22  -  []  116.94 5.84 0 top
NOREF#23  -  []  91.54 26.8 0 top
NOREF#24  -  []  -127.66 -149.22 0 top
NOREF#25  -  []  82.65 4.57 90 top
NOREF#26  -  []  48.74 55.47 90 top
NOREF#27  -  []  46.2 52.93 90 top
NOREF#28  -  []  82.65 5.84 0 top
NOREF#29  -  []  67.05 53.22 0 top
NOREF#30  -  []  35.41 52.93 90 top
NOREF#31  -  []  154.69 0.89 0 top
NOREF#32  -  []  91.4 56.79 0 top
NOREF#33  -  []  0 68.58 0 top
NOREF#34  -  []  89.41 -32.49 0 top
NOREF#35  -  []  36.8 12.83 90 top
NOREF#36  -  []  9.02 40.17 0 top
NOREF#37  -  []  105.05 11.23 180 bottom
PP1  PROBE POINT  [PROBE_POINT_30PAD]  33.1 2.18 0 top
PP3  PROBE POINT  [PROBE_POINT_30PAD]  30.78 16.99 0 top
PP5  PROBE POINT  [PROBE_POINT_30PAD]  33.02 14.35 0 top
PP7  PROBE POINT  [PROBE_POINT_30PAD]  54.23 14.45 0 top
PP8  PROBE POINT  [PROBE_POINT_30PAD]  30.12 10.01 0 top
PP11  PROBE POINT  [PROBE_POINT_30PAD]  32.38 8 0 top
PP13  PROBE POINT  [PROBE_POINT_30PAD]  42.16 9.78 0 top
PP15  PROBE POINT  [PROBE_POINT_30PAD]  43.18 13.59 0 top
PP22  PROBE POINT  [PROBE_POINT_22PAD]  98.76 32.38 90 top
PP23  PROBE POINT  [PROBE_POINT_30PAD]  106.68 13.59 0 top
PP27  PROBE POINT  [PROBE_POINT_22PAD]  42.09 48.95 0 top
PP28  PROBE POINT  [PROBE_POINT_22PAD]  30.38 49.38 0 top
PP29  PROBE POINT  [PROBE_POINT_22PAD]  29.74 63.07 0 top
PP30  PROBE POINT  [PROBE_POINT_22PAD]  29.69 61.04 0 top
PP31  PROBE POINT  [PROBE_POINT_30PAD]  115.49 48.69 0 top
PP32  PROBE POINT  [PROBE_POINT_30PAD]  129.26 48.51 0 top
PP33  PROBE POINT  [PROBE_POINT_30PAD]  122.71 48.67 0 top
PP34  PROBE POINT  [PROBE_POINT_30PAD]  155.68 35.69 0 top
PP35  PROBE POINT  [PROBE_POINT_30PAD]  155.68 28.7 0 top
PP36  PROBE POINT  [PROBE_POINT_30PAD]  155.68 19.81 0 top
PP37  PROBE POINT  [PROBE_POINT_30PAD]  155.68 9.02 0 top
PP38  PROBE POINT  [PROBE_POINT_30PAD]  155.68 54.1 0 top
PP39  PROBE POINT  [PROBE_POINT_30PAD]  155.68 64.26 0 top
PP41  PROBE POINT  [PROBE_POINT_30PAD]  155.68 3.3 0 top
PP42  PROBE POINT  [PROBE_POINT_30PAD]  155.68 14.73 0 top
PP43  PROBE POINT  [PROBE_POINT_30PAD]  155.68 44.58 0 top
PP44  PROBE POINT  [PROBE_POINT_30PAD]  155.68 47.75 0 top
PP45  PROBE POINT  [PROBE_POINT_30PAD]  155.68 40.13 0 top
PP46  PROBE POINT  [PROBE_POINT_30PAD]  155.68 24.89 0 top
PP47  PROBE POINT  [PROBE_POINT_30PAD]  155.68 50.93 0 top
PP48  PROBE POINT  [PROBE_POINT_30PAD]  155.68 61.09 0 top
PP49  PROBE POINT  [PROBE_POINT_30PAD]  155.68 57.28 0 top
PP50  PROBE POINT  [PROBE_POINT_30PAD]  155.68 6.48 0 top
PP51  PROBE POINT  [PROBE_POINT_30PAD]  155.68 33.15 0 top
PP52  PROBE POINT  [PROBE_POINT_30PAD]  57.53 17.27 0 top
Q1  DTC114EET1G  [SOT_416_3_63X31]  139.12 34.19 90 top
Q2  DTC114EET1G  [SOT_416_3_63X31]  139.12 41.53 90 top
Q4  CSD18532Q5  [SON_Q5B_8]  130.71 8.46 0 bottom
R1  17.8  [0201]  14.12 15.9 270 top
R2  294  [0201]  13.82 14.96 180 top
R3  294  [0201]  13.82 16.84 180 top
R16  0  [0201]  21.36 16.43 90 top
R17  0  [0201]  20.75 16.43 90 top
R20  0  [0402]  9.88 29.53 315 top
R21  0  [0402]  10.5 28.22 225 top
R22  0  [0402]  8.57 30.13 225 top
R23  0  [0402]  9.87 21.03 45 top
R24  0  [0402]  10.47 22.34 135 top
R25  0  [0402]  8.56 20.42 135 top
R30  1K  [0402]  103.63 8.89 0 top
R31  3.65k  [0201]  11.96 20.93 180 top
R38  10K  [0402]  77.77 51.26 0 bottom
R39  10K  [0402]  77.77 47.14 0 bottom
R45  100  [0201]  29.64 55.78 90 top
R47  1k  [0201]  96.75 6.96 180 top
R49  10k  [0201]  96.77 8.89 0 top
R50  10k  [0201]  37.8 54.08 270 bottom
R51  0  [0201]  29.08 62.36 0 top
R52  100  [0201]  30.02 62.05 90 top
R53  0  [0201]  29.08 61.75 0 top
R54  0  [0603]  20.17 52.83 0 top
R55  0  [0603]  20.17 50.29 0 top
R56  0  [0603]  20.17 66.8 0 top
R57  0  [0603]  20.17 64.26 0 top
R58  49.9  [0201]  68.5 52.5 0 bottom
R59  49.9  [0201]  67.23 52.5 180 bottom
R60  12k  [0402]  72.16 44.48 0 top
R61  49.9  [0201]  63.02 50.8 225 bottom
R62  49.9  [0201]  63.92 51.69 45 bottom
R63  0  [0201]  66.27 50.22 90 top
R64  680  [0201]  73.41 50.5 180 top
R67  680  [0201]  72.06 50.42 135 top
R68  0  [0201]  75.34 48.54 180 bottom
R69  12  [0201]  73.79 48.23 270 bottom
R70  150  [0201]  75.34 47.93 180 bottom
R71  120  [0201]  28.7 44.73 270 bottom
R72  120  [0201]  28.7 46 90 bottom
R73  24.9K  [0201]  63.53 40.54 270 top
R74  100  [0201]  28.37 43.18 180 bottom
R75  100  [0201]  28.37 43.79 180 bottom
R76  39k  [0201]  39.95 49.53 90 bottom
R77  240  [0201]  29.18 38.2 90 bottom
R78  240  [0201]  29.18 36.93 270 bottom
R79  200  [0201]  29.34 42.85 270 bottom
R80  200  [0201]  29.34 44.12 90 bottom
R81  100  [0201]  27.43 42.85 90 bottom
R82  100  [0201]  27.43 44.12 270 bottom
R83  49.9  [0402]  19.56 59.03 270 top
R84  49.9  [0402]  19.56 57.25 270 top
R85  0  [0201]  27.64 39.17 180 bottom
R86  0  [0201]  27.64 39.78 180 bottom
R87  620  [0201]  39.95 40.87 90 top
R89  240  [0201]  28.57 40.11 90 bottom
R90  240  [0201]  28.57 38.84 270 bottom
R93  49.9  [0402]  44.17 43.76 90 bottom
R94  120  [0201]  36.16 49 180 bottom
R95  120  [0201]  37.43 49 0 bottom
R96  0  [0201]  34.54 49.42 90 bottom
R99  0  [0201]  35.19 49.42 90 bottom
R100  200  [0201]  34.22 48.35 180 bottom
R101  200  [0201]  35.52 48.36 0 bottom
R102  100  [0201]  35.53 50.37 0 bottom
R103  100  [0201]  34.22 50.39 180 bottom
R104  130  [0201]  48.49 36.19 270 bottom
R105  240  [0201]  38.74 34.73 0 bottom
R106  240  [0201]  37.45 34.73 180 bottom
R107  100  [0201]  50.7 35.86 180 bottom
R108  82  [0201]  51.64 36.19 90 bottom
R109  49.9  [0201]  47.89 36.19 90 bottom
R110  240  [0201]  40.02 34.72 180 bottom
R111  240  [0201]  41.31 34.72 0 bottom
R112  130  [0201]  48.49 34.92 90 bottom
R113  100  [0201]  50.7 35.25 180 bottom
R114  82  [0201]  51.64 34.92 270 bottom
R115  0  [0201]  33.48 33.33 270 bottom
R116  49.9  [0201]  47.89 34.92 270 bottom
R117  240  [0201]  33.81 34.3 0 bottom
R118  0  [0201]  32.84 33.33 270 bottom
R119  240  [0201]  32.51 34.3 180 bottom
R120  240  [0201]  45.24 42.27 90 bottom
R121  240  [0201]  45.24 41 270 bottom
R122  1.3K  [0201]  32.28 39.62 180 top
R123  0  [0402]  30.76 40.13 0 top
R124  750  [0402]  45.75 37.64 180 top
R125  750  [0402]  45.77 35.53 180 top
R126  750  [0402]  45.72 44.09 180 top
R127  750  [0402]  45.75 39.78 180 top
R128  1K  [0402]  138.48 35.43 0 bottom
R129  0  [0402]  138.89 33.68 90 bottom
R131  1K  [0402]  138.46 42.49 0 bottom
R132  0  [0402]  138.89 41 90 bottom
R136  0  [0402]  111.87 45.68 180 bottom
R137  3.01K  [0402]  106.6 46.42 0 bottom
R138  0  [0201]  133.43 21.11 90 bottom
R139  10  [0201]  135.36 19.53 90 bottom
R140  22  [0201]  97.28 38.62 90 top
R141  22  [0201]  96.75 40.96 270 top
R142  10  [0201]  134.72 19.53 90 bottom
R143  22  [0201]  96.26 38.62 90 top
R144  22  [0201]  95.76 40.93 270 top
R145  22  [0201]  95.27 38.62 90 top
R146  4.7K  [0201]  106.07 42.64 180 top
R147  12k  [0201]  102.49 46.65 180 top
R148  22  [0201]  94.28 38.62 90 top
R150  1k  [0201]  104.8 42.64 180 top
R151  10k  [0201]  106.07 43.25 180 top
R155  10k  [0201]  101.27 52.18 90 top
R156  10k  [0201]  100.69 52.18 90 top
R157  10k  [0201]  98.7 49.58 0 top
R159  2.2k  [0201]  98.55 48.96 180 top
R160  1k  [0402]  127.51 13.34 0 bottom
R161  48.7k  [0402]  41.1 6.73 90 bottom
R163  100k  [0402]  42.01 6.73 90 bottom
R168  41.2k  [0402]  91.97 13.44 180 top
R169  162k  [0402]  93.75 13.44 0 top
R171  205k  [0402]  88.32 12.01 270 bottom
R173  162k  [0402]  89.23 12.01 270 bottom
R176  0  [1206]  51.56 7.85 0 top
R180  0  [0402]  60.6 8.71 0 top
R182  0  [0402]  61.98 6.93 0 bottom
R188  0  [0402]  111.94 40.49 0 top
R189  0  [0402]  111.94 41.4 0 top
R190  0  [0402]  110.95 42.32 0 top
R199  221K  [0402]  116.13 42.01 180 top
R200  162k  [0402]  116.13 41.1 0 top
R202  71.5k  [0402]  130.94 42.09 180 top
R203  162k  [0402]  130.94 41.17 0 top
R205  71.5k  [0402]  123.49 42.14 180 top
R206  162k  [0402]  123.49 41.22 0 top
R207  0  [0402]  116.13 40.18 180 top
R208  0  [0402]  116.13 39.27 180 top
R209  0  [0402]  130.94 40.26 180 top
R210  0  [0402]  130.94 39.34 180 top
R211  0  [0402]  123.49 40.31 180 top
R212  0  [0402]  123.49 39.4 180 top
R213  10K  [0402]  79.27 40.39 0 bottom
R214  10K  [0402]  79.27 44.37 0 bottom
R215  10K  [0402]  81 33.45 0 bottom
R216  10K  [0402]  81.03 37.47 0 bottom
R217  0  [0402]  43.84 6.73 90 bottom
R218  0  [0402]  42.93 6.73 90 bottom
R219  511k  [0402]  111.25 11.53 180 top
R220  162k  [0402]  111.25 10.52 0 top
R224  0  [0805]  104.37 37.03 90 top
R225  0  [0805]  104.36 35 90 top
R228  0  [0201]  28.37 58.55 90 top
R229  0  [0201]  30.25 58.55 90 top
R230  0  [0402]  69.27 36.32 180 top
R231  0  [0402]  69.24 34.14 180 top
R232  0  [0402]  69.27 37.41 180 top
R233  0  [0402]  69.24 35.26 180 top
R234  100  [0201]  44.04 47.52 90 bottom
R236  0  [0805]  33.99 2.41 0 bottom
R237  0  [0805]  39.12 17.53 0 top
R238  0  [0805]  82.83 7.11 270 bottom
R239  0  [0402]  19.63 28.91 180 bottom
R248  0  [0201]  93.24 49.48 270 top
R249  0  [0201]  95.48 49.25 90 top
R250  0  [0201]  96.19 49.25 90 top
R251  0  [0201]  96.95 49.25 90 top
R254  1.27K  [0402]  61.93 7.8 0 top
R256  10K  [0402]  61.93 6.88 180 top
R292  0  [0201]  93.24 50.09 90 top
R293  0  [0201]  95.48 48.64 270 top
R294  0  [0201]  96.19 48.64 270 top
R295  0  [0201]  96.95 48.64 270 top
R296  0  [0201]  93.24 51.97 90 top
R297  0  [0201]  95.48 45.85 270 top
R298  0  [0201]  99.26 52.17 270 top
R299  0  [0201]  96.19 45.85 270 top
R300  0  [0201]  93.24 51.36 270 top
R301  0  [0201]  96.19 46.46 90 top
R302  0  [0201]  95.48 46.46 90 top
R303  0  [0201]  103.38 52.48 0 top
R304  0  [0201]  84.56 42.62 90 top
R305  0  [0201]  83.62 42.6 90 top
R306  0  [0201]  83.59 44.88 90 top
R307  0  [0201]  84.58 44.86 90 top
R308  0  [0201]  83.59 44.27 270 top
R309  0  [0201]  84.56 42.01 270 top
R310  0  [0201]  83.62 41.99 270 top
R311  0  [0201]  84.58 44.25 270 top
R312  0  [0201]  104.19 41.66 180 top
R313  0  [0201]  102.08 40.61 180 top
R314  0  [0201]  101.6 39.78 180 top
R315  0  [0201]  101.07 38.94 180 top
R316  0  [0201]  102.69 40.61 180 top
R317  0  [0201]  101.68 38.94 180 top
R318  0  [0201]  102.21 39.78 180 top
R319  0  [0201]  104.8 41.66 180 top
R326  0  [0402]  89.97 38.33 90 top
R327  0  [0402]  89.97 39.37 270 top
R328  0  [0201]  99.77 41.12 270 top
R329  0  [0201]  94.28 38.02 90 top
R330  0  [0201]  99.77 40.51 270 top
R331  0  [0201]  21.59 27.59 225 bottom
R332  100k  [0402]  133.3 38.94 90 bottom
R334  0  [0402]  65.56 7.32 270 bottom
R335  0  [0402]  64.64 7.32 270 bottom
R336  0  [0402]  90.14 12.01 270 bottom
R337  0  [0402]  91.06 12.01 270 bottom
R338  0  [0402]  96.34 14.66 0 top
R339  0  [0402]  96.34 13.72 0 top
R340  0  [0402]  113.67 8.1 0 top
R341  0  [0402]  111.25 9.25 180 top
R342  0  [0402]  113.94 39.6 270 bottom
R343  0  [0402]  113.96 39.61 270 top
R354  0  [0402]  70.48 8.66 0 top
R355  0  [0402]  69.14 9.09 90 top
R356  0  [0805]  117.93 47.8 270 top
R357  0  [0805]  132.79 47.75 270 top
R358  0  [0805]  125.32 47.85 270 top
R359  0  [0402]  59.92 36.09 0 top
R360  0  [0805]  36.32 12.06 180 top
R361  0  [0805]  37.34 11.05 90 top
R362  0  [0402]  86.92 11.56 180 bottom
R363  0  [0402]  87.4 12.01 90 bottom
R364  0  [0402]  60.07 7.75 0 top
R365  0  [0402]  60.55 7.32 270 top
SW1  SWITCH, SMT, PUSHBUTTON  [SW_SMVT_SPST_EVQPJX_2]  106.93 6.22 90 top
SW2  SWITCH, SMT, PUSHBUTTON  [SW_SMVT_SPST_EVQPJX_2]  99.69 6.22 90 top
T3  TC1-1-43X+  [TFMR_5_150X150_50]  16.31 58.14 0 top
T4  TC1-1-43X+  [TFMR_5_150X150_50]  20.17 51.56 0 top
T5  TC1-1-43X+  [TFMR_5_150X150_50]  25.88 51.56 180 top
T6  TC1-1-43X+  [TFMR_5_150X150_50]  20.17 65.53 0 top
T7  TC1-1-43X+  [TFMR_5_150X150_50]  25.88 65.53 180 top
TP1  BLK  [TP_THVT_060_RND]  151.66 65.74 0 top
TP2  BLK  [TP_THVT_060_RND]  6.53 9.8 0 top
TP3  YELLOW  [TP_THVT_060_RND]  11.61 33.02 0 top
TP5  RED  [TP_THVT_060_RND]  14.5 62.53 0 top
TP6  BLK  [TP_THVT_060_RND]  20.27 47.6 0 top
TP7  BLK  [TP_THVT_060_RND]  88.27 17.78 0 top
TP8  BLK  [TP_THVT_060_RND]  44.15 49.73 0 top
TP9  BLK  [TP_THVT_060_RND]  120.42 45.82 0 top
TP10  Testloop_Red  [TESTPOINT_62DIA]  125.86 2.41 0 top
TP11  Testloop_Black  [TESTPOINT_62DIA]  151.99 2.36 0 top
TP14  BLK  [TP_THVT_060_RND]  76.07 44.86 0 top
TP15  YELLOW  [TP_THVT_060_RND]  6.12 25.27 0 top
U1  DAC38RF80  [BGA_144_10MMX10MM_0P80MM]  18.65 24.47 90 top
U2  ADC32RF80  [QFN_72_10MMX10MM_0P50MM_PWRPAD]  36.04 58.55 270 top
U3  MASW_009444  [PDFN_6_P35MM]  27.41 60.17 270 top
U4  MASW_009444  [PDFN_6_P35MM]  27.43 57.84 270 top
U5  LMX2582  [QFN40_RTA_RTB_RHA]  69.31 47.68 90 bottom
U7  LMK04828  [QFN_64_360X360_0P50MM_PWRPAD]  36.21 41.38 0 bottom
U8  LP5907-3.3  [DBV5]  112.33 47.34 90 top
U10  FT4232H  [LQFP_64_402X402_20]  98.02 45.41 180 bottom
U11  TXS0108E  [QFN_20_183X144_RGY]  87.36 43.41 90 bottom
U12  93LC46B-I/MS  [MSOP_8_118X118_26]  99.2 45.13 270 top
U14  TPS2400  [DBV5]  131.44 12.83 180 bottom
U15  LM27761  [SON_DSG_8]  43.94 3.84 90 bottom
U17  TPS82085  [USIL_8_3MMX2P8MM_0P65MM]  93.7 15.67 180 top
U19  TPS82085  [USIL_8_3MMX2P8MM_0P65MM]  89.64 9.35 180 bottom
U21  TPS7A8500  [QFN20_RGR_P5MM]  65.52 8.57 0 top
U22  TPS7A4700  [QFN_20_199X199_0P65MM]  110.29 39.98 0 bottom
U23  TPS82085  [USIL_8_3MMX2P8MM_0P65MM]  113.92 10.39 90 top
U24  TPS82085  [USIL_8_3MMX2P8MM_0P65MM]  118.8 40.56 90 top
U25  TPS82085  [USIL_8_3MMX2P8MM_0P65MM]  133.63 40.54 90 top
U26  TPS82085  [USIL_8_3MMX2P8MM_0P65MM]  126.16 40.61 90 top
U27  MASW_009444  [PDFN_6_P35MM]  24.69 59.94 0 top
U28  MASW_009444  [PDFN_6_P35MM]  24.69 57.56 0 top
U29  MASW_009444  [PDFN_6_P35MM]  22.1 59.79 270 top
U30  MASW_009444  [PDFN_6_P35MM]  22.05 57.45 270 top
U31  TXB0108  [QFN_20_183X144_RGY]  86.89 36.83 270 top
U32  TXS0108E  [QFN_20_183X144_RGY]  87.38 49.56 270 top
Y1  122.88MHz  [VCXO_6_CUSTOM]  59.18 36.86 180 bottom
Y2  12MHz w/ 10pF  [XTAL_4_SM_130X102]  107.44 50.91 270 top

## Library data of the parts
C1 C186 C188 C190 C191 C196 C197 C254 C275 C279 C281-C283 C285 C295 C299 C308 C314 C317 C318 C324 C326 C340 C344 C347 C365 C367 C379 C425 C437 C442 = CAP NP_1: tolerance: 10%
C7 C9-C25 C32-C42 C45 C46 C49 C50 C53 C54 C57 C58 C61 C62 C65 C66 C69 C70 C73 C74 C77 C78 C81 C82 C85 C86 C88 C91 C92 C96 C99 C100 C103 C106-C109 C112-C122 C128-C134 C139 C142 C143 C146 C147 C157 C247 C257 C360 C361 C423 C424 = CAP0402_0: tolerance: 10%
C26 C27 C29 C31 C48 C52 C56 C60 C64 C68 C72 C76 C80 C84 C87 C90 C94 C98 C102 C105 C172 C173 C176 C177 C179 C180 C182 C185 C199 C201 C216 C217 C223 C224 C226 C230-C241 C243-C246 C249-C251 C253 C255 C260 C261 C264 C265 C268 C277 C313 C327 C341 C342 C436 C438 C439 C441 = CAPACITOR_NP_1: tolerance: 10%
C28 = CAP_0402_0.001uF_H
C30 C43 C47 C51 C55 C59 C63 C67 C71 C75 C79 C83 C89 C93 C95 C97 C101 C104 C280 C289 C298 C301 C303 C346 C364 C378 C382 C443 = CAP0201_0: tolerance: 20%
C44 = CAPACITOR_NP_1: tolerance: 20%
C110 C111 C123-C127 C135-C138 C140 C141 C148-C150 = CAP_0201_0.1uF: tolerance: 10%
C144 C145 = CAP0402_0: tolerance: +/-10%
C153 C203 = CAP NP_0: tolerance: 5%
C154 C343 C355 = CAP0603: tolerance: 10%
C158-C167 = CAP_0603_0.1uF_H: tolerance: 10%
C168 C170 C171 C178 C181 C184 C207 C208 C219 C427-C434 C445-C448 = CAP_0603_100pF_H
C174 C183 C187 C189 C248 C258 = CAP NP_0: tolerance: 20%
C192-C195 C198 C200 C202 C221 C228 C273 C276 C309 C315 C316 C320 C325 C348 C435 C440 = CAP NP_0: tolerance: 10%
C204 C206 C383 C384 = CAP_0402_0.01uF_H: tolerance: 10%
C218 C220 C227 = CAP_0402_0.1uF_H: tolerance: 10%
C222 = CAP_0402_2200pF_H
C225 = CAP_0402_10pF_H
C229 = CAPACITOR_NP_1: tolerance: 2%
C242 = CAP NP_2: tolerance: 20%
C252 C256 C262 C278 C288 C297 C300 C302 C362 C377 C381 = CAP NP_1: tolerance: 20%
C259 C263 = CAP_1206
C266 C267 = CAP NP: tolerance: 2%
C269 C270 = CAP NP: tolerance: 5%
C274 C426 = CAP_1210_22uF
C290 C294 C366 C376 C380 = CAP_1210_22uF: tolerance: 10%
C345 = CAP0201_0: tolerance: 10%
C353 = CAP0201: tolerance: 20%
C354 C358 = CAP0201: tolerance: 10%
C356 C359 = CAP0402_0: tolerance: 10V
C444 = CAPACITOR POL: tolerance: 20%
D1-D7 = LED
D9 = LED_AMBER_1206
D10 = LED_GREEN_1206
F1 = FUSE_0
FB1-FB11 FB21-FB27 FB38 FB39 FB47-FB52 = FERRITE_BEAD_0402_H
FB12 FB14-FB16 FB44 FB45 = FERRITE_BEAD
FB13 FB17 FB18 FB20 FB37 FB40-FB42 FB53 = BEAD_NFM31P
HS1 = HEATSINK_1
HS2 = HEATSINK_2
J1 J3 J4 = TMP_122841
J5 = Header_2x5_100_0
J8 J13 = SMP_PLUG_SMT_0
J9 J10 = SMA-END_PLUG_ROUND
J12 = SMA-THVT_142-0701-201_REC
J14 = CON_SMVT_40X10_ASP-134487-01
J15 = USB_MINI_AB_VERT
J17 = PWR_JACK_PJ006B
J38 = HEADER 2/SM
JP1-JP4 JP7 JP8 = Jumper_1x3_100_0
JP5 JP6 = HDR_2x1_100
L10-L19 = CHOKE
MT1-MT3 = MOUNTING_HOLE
PP1 PP3 PP5 PP7 PP8 PP22 PP23 PP27-PP39 PP41-PP52 = PROBE_POINT_2
PP11 PP13 PP15 = PROBE_POINT_0
Q1 Q2 = MMBT2222A
Q4 = CSD18532Q5B
R1-R3 = RES0603: tolerance: 1%
R16 R17 R21 R22 R24 R25 R51 R53 R63 R123 R136-R138 R180 R182 R188-R190 R207-R212 R217 R218 R228 R229 R326 R327 R331 R334-R343 R354 R355 R359 R362-R365 = R: tolerance: 5%
R20 R23 R139-R145 R148 R239 R248-R251 R292-R319 R328-R330 = Res_0402_10_H
R30 R47 R49 R50 R150 R151 R155-R157 R254 = R_0: tolerance: 1%
R31 = Res_0402_1.8K
R38 R39 R70 R76 R87 R213-R216 = R_1: tolerance: 1%
R45 = Res_0201_200_H: tolerance: 1%
R52 = Res_0201_H: tolerance: 1%
R54-R57 = Res_0603_Zero_H_DNI
R58 R59 R61 R62 R64 R67 = Res_0402_49.9: tolerance: 1%
R60 R69 = Res_0402_18
R68 R74 R75 R81 R82 R85 R86 R96 R99 R115 R118 R176 R224 R225 R234 R236-R238 R356-R358 R360 R361 = Res_0402_Zero_H_DNI
R71 R72 R77-R80 R89 R90 R94 R95 R100 R101 R105 R106 R110 R111 R117 R119-R121 = Res_0402_249
R73 = Res_0402_24.9
R83 R84 R93 = Res_0402_49.9
R102 R103 = Res_0603_100
R104 R108 R109 R112 R114 R116 = RESISTOR_0: tolerance: 1%
R107 R113 = Res_0402_100_H
R122 R124-R127 = RESISTOR_0
R128 R131 R147 R161 R163 R169 R173 R200 R203 R206 R220 R332 = R: tolerance: 1%
R129 R132 R168 R171 R199 R202 R205 R219 R230-R233 = Res_0603_Zero_H
R146 R159 = RESISTOR
R160 = Res_0402_1k
R256 = RESISTOR: tolerance: 1%
SW1 SW2 = SPST_EVQ-PJ
T3-T7 = BALUN_TC1-1-43X+
TP1 TP2 TP6-TP9 TP14 = TESTPOINT_BLK
TP3 TP15 = TESTPOINT_BLUE
TP5 = TESTPOINT_RED
TP10 TP11 = TESTLOOP_BLACK
U1 = DAC38RF80_10x10
U2 = ADC32RFXX_72QFN
U3 U4 U27-U30 = RF_SWITCH_MASW_009444
U5 = LMX2582_LM2592_1
U7 = LMK04828
U8 = LP5907
U10 = FT4232H_2
U11 U31 U32 = TXS0108E
U12 = EEPROM
U14 = TPS2400
U15 = LM27761
U17 U19 U23-U26 = TPS82085
U21 = TPS7A8500
U22 = TPS7A4700
Y1 = OSC_SM_6_TCO-2100-SERIES_2
Y2 = CRYSTAL1-4/SM

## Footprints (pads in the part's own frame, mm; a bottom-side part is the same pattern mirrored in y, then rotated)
0201
  rect 0.305x0.305 smd: 1(-0.305,0) 2(0.305,0)
0306
  rect 0.356x1.626 smd: 1(-0.363,0) 2(0.363,0)
0402
  rect 0.508x0.635 smd: 1(-0.508,0) 2(0.508,0)
0508
  rect 0.559x2.007 smd: 1(-0.593,0) 2(0.593,0)
0603
  rect 0.762x0.787 smd: 1(-0.787,0) 2(0.787,0)
0805
  rect 1.016x1.27 smd: 1(-1.016,0) 2(1.016,0)
1206
  rect 1.321x1.6 smd: 1(-1.524,0) 2(1.524,0)
1206_BEAD_NFM31P
  rect 1.016x1.575 smd: 1(-1.778,0) 3(1.778,0)
  rect 1.321x2.032 smd: 2(0,0)
1210
  rect 0.965x2.489 smd: 1(-1.372,0) 2(1.372,0)
7343
  rect 2.388x2.642 smd: 1(-3.404,0) 2(3.404,0)
BGA_144_10MMX10MM_0P80MM
  round 0.457 smd: A1(-4.4,-4.4) A2(-4.4,-3.6) A3(-4.4,-2.8) A4(-4.4,-2) A5(-4.4,-1.2) A6(-4.4,-0.4) A7(-4.4,0.4) A8(-4.4,1.2) A9(-4.4,2) A10(-4.4,2.8) A11(-4.4,3.6) A12(-4.4,4.4) B1(-3.6,-4.4) B2(-3.6,-3.6) B3(-3.6,-2.8) B4(-3.6,-2) B5(-3.6,-1.2) B6(-3.6,-0.4) B7(-3.6,0.4) B8(-3.6,1.2) B9(-3.6,2) B10(-3.6,2.8) B11(-3.6,3.6) B12(-3.6,4.4) C1(-2.8,-4.4) C2(-2.8,-3.6) C3(-2.8,-2.8) C4(-2.8,-2) C5(-2.8,-1.2) C6(-2.8,-0.4) C7(-2.8,0.4) C8(-2.8,1.2) C9(-2.8,2) C10(-2.8,2.8) C11(-2.8,3.6) C12(-2.8,4.4) D1(-2,-4.4) D2(-2,-3.6) D3(-2,-2.8) D4(-2,-2) D5(-2,-1.2) D6(-2,-0.4) D7(-2,0.4) D8(-2,1.2) D9(-2,2) D10(-2,2.8) D11(-2,3.6) D12(-2,4.4) E1(-1.2,-4.4) E2(-1.2,-3.6) E3(-1.2,-2.8) E4(-1.2,-2) E5(-1.2,-1.2) E6(-1.2,-0.4) E7(-1.2,0.4) E8(-1.2,1.2) E9(-1.2,2) E10(-1.2,2.8) E11(-1.2,3.6) E12(-1.2,4.4) F1(-0.4,-4.4) F2(-0.4,-3.6) F3(-0.4,-2.8) F4(-0.4,-2) F5(-0.4,-1.2) F6(-0.4,-0.4) F7(-0.4,0.4) F8(-0.4,1.2) F9(-0.4,2) F10(-0.4,2.8) F11(-0.4,3.6) F12(-0.4,4.4) G1(0.4,-4.4) G2(0.4,-3.6) G3(0.4,-2.8) G4(0.4,-2) G5(0.4,-1.2) G6(0.4,-0.4) G7(0.4,0.4) G8(0.4,1.2) G9(0.4,2) G10(0.4,2.8) G11(0.4,3.6) G12(0.4,4.4) H1(1.2,-4.4) H2(1.2,-3.6) H3(1.2,-2.8) H4(1.2,-2) H5(1.2,-1.2) H6(1.2,-0.4) H7(1.2,0.4) H8(1.2,1.2) H9(1.2,2) H10(1.2,2.8) H11(1.2,3.6) H12(1.2,4.4) J1(2,-4.4) J2(2,-3.6) J3(2,-2.8) J4(2,-2) J5(2,-1.2) J6(2,-0.4) J7(2,0.4) J8(2,1.2) J9(2,2) J10(2,2.8) J11(2,3.6) J12(2,4.4) K1(2.8,-4.4) K2(2.8,-3.6) K3(2.8,-2.8) K4(2.8,-2) K5(2.8,-1.2) K6(2.8,-0.4) K7(2.8,0.4) K8(2.8,1.2) K9(2.8,2) K10(2.8,2.8) K11(2.8,3.6) K12(2.8,4.4) L1(3.6,-4.4) L2(3.6,-3.6) L3(3.6,-2.8) L4(3.6,-2) L5(3.6,-1.2) L6(3.6,-0.4) L7(3.6,0.4) L8(3.6,1.2) L9(3.6,2) L10(3.6,2.8) L11(3.6,3.6) L12(3.6,4.4) M1(4.4,-4.4) M2(4.4,-3.6) M3(4.4,-2.8) M4(4.4,-2) M5(4.4,-1.2) M6(4.4,-0.4) M7(4.4,0.4) M8(4.4,1.2) M9(4.4,2) M10(4.4,2.8) M11(4.4,3.6) M12(4.4,4.4)
CON_SMVT_40X10_SEAM_MTG
  round 3.81 hole 2.692: (-31.496,-2.007) (31.496,-2.007)
  round 1.27 hole 1.27 unplated: (-27.191,-3.048) (27.191,0)
  round 0.635 smd: A1(24.765,5.715) A2(23.495,5.715) A3(22.225,5.715) A4(20.955,5.715) A5(19.685,5.715) A6(18.415,5.715) A7(17.145,5.715) A8(15.875,5.715) A9(14.605,5.715) A10(13.335,5.715) A11(12.065,5.715) A12(10.795,5.715) A13(9.525,5.715) A14(8.255,5.715) A15(6.985,5.715) A16(5.715,5.715) A17(4.445,5.715) A18(3.175,5.715) A19(1.905,5.715) A20(0.635,5.715) A21(-0.635,5.715) A22(-1.905,5.715) A23(-3.175,5.715) A24(-4.445,5.715) A25(-5.715,5.715) A26(-6.985,5.715) A27(-8.255,5.715) A28(-9.525,5.715) A29(-10.795,5.715) A30(-12.065,5.715) A31(-13.335,5.715) A32(-14.605,5.715) A33(-15.875,5.715) A34(-17.145,5.715) A35(-18.415,5.715) A36(-19.685,5.715) A37(-20.955,5.715) A38(-22.225,5.715) A39(-23.495,5.715) A40(-24.765,5.715) B1(24.765,4.445) B2(23.495,4.445) B3(22.225,4.445) B4(20.955,4.445) B5(19.685,4.445) B6(18.415,4.445) B7(17.145,4.445) B8(15.875,4.445) B9(14.605,4.445) B10(13.335,4.445) B11(12.065,4.445) B12(10.795,4.445) B13(9.525,4.445) B14(8.255,4.445) B15(6.985,4.445) B16(5.715,4.445) B17(4.445,4.445) B18(3.175,4.445) B19(1.905,4.445) B20(0.635,4.445) B21(-0.635,4.445) B22(-1.905,4.445) B23(-3.175,4.445) B24(-4.445,4.445) B25(-5.715,4.445) B26(-6.985,4.445) B27(-8.255,4.445) B28(-9.525,4.445) B29(-10.795,4.445) B30(-12.065,4.445) B31(-13.335,4.445) B32(-14.605,4.445) B33(-15.875,4.445) B34(-17.145,4.445) B35(-18.415,4.445) B36(-19.685,4.445) B37(-20.955,4.445) B38(-22.225,4.445) B39(-23.495,4.445) B40(-24.765,4.445) C1(24.765,3.175) C2(23.495,3.175) C3(22.225,3.175) C4(20.955,3.175) C5(19.685,3.175) C6(18.415,3.175) C7(17.145,3.175) C8(15.875,3.175) C9(14.605,3.175) C10(13.335,3.175) C11(12.065,3.175) C12(10.795,3.175) C13(9.525,3.175) C14(8.255,3.175) C15(6.985,3.175) C16(5.715,3.175) C17(4.445,3.175) C18(3.175,3.175) C19(1.905,3.175) C20(0.635,3.175) C21(-0.635,3.175) C22(-1.905,3.175) C23(-3.175,3.175) C24(-4.445,3.175) C25(-5.715,3.175) C26(-6.985,3.175) C27(-8.255,3.175) C28(-9.525,3.175) C29(-10.795,3.175) C30(-12.065,3.175) C31(-13.335,3.175) C32(-14.605,3.175) C33(-15.875,3.175) C34(-17.145,3.175) C35(-18.415,3.175) C36(-19.685,3.175) C37(-20.955,3.175) C38(-22.225,3.175) C39(-23.495,3.175) C40(-24.765,3.175) D1(24.765,1.905) D2(23.495,1.905) D3(22.225,1.905) D4(20.955,1.905) D5(19.685,1.905) D6(18.415,1.905) D7(17.145,1.905) D8(15.875,1.905) D9(14.605,1.905) D10(13.335,1.905) D11(12.065,1.905) D12(10.795,1.905) D13(9.525,1.905) D14(8.255,1.905) D15(6.985,1.905) D16(5.715,1.905) D17(4.445,1.905) D18(3.175,1.905) D19(1.905,1.905) D20(0.635,1.905) D21(-0.635,1.905) D22(-1.905,1.905) D23(-3.175,1.905) D24(-4.445,1.905) D25(-5.715,1.905) D26(-6.985,1.905) D27(-8.255,1.905) D28(-9.525,1.905) D29(-10.795,1.905) D30(-12.065,1.905) D31(-13.335,1.905) D32(-14.605,1.905) D33(-15.875,1.905) D34(-17.145,1.905) D35(-18.415,1.905) D36(-19.685,1.905) D37(-20.955,1.905) D38(-22.225,1.905) D39(-23.495,1.905) D40(-24.765,1.905) E1(24.765,0.635) E2(23.495,0.635) E3(22.225,0.635) E4(20.955,0.635) E5(19.685,0.635) E6(18.415,0.635) E7(17.145,0.635) E8(15.875,0.635) E9(14.605,0.635) E10(13.335,0.635) E11(12.065,0.635) E12(10.795,0.635) E13(9.525,0.635) E14(8.255,0.635) E15(6.985,0.635) E16(5.715,0.635) E17(4.445,0.635) E18(3.175,0.635) E19(1.905,0.635) E20(0.635,0.635) E21(-0.635,0.635) E22(-1.905,0.635) E23(-3.175,0.635) E24(-4.445,0.635) E25(-5.715,0.635) E26(-6.985,0.635) E27(-8.255,0.635) E28(-9.525,0.635) E29(-10.795,0.635) E30(-12.065,0.635) E31(-13.335,0.635) E32(-14.605,0.635) E33(-15.875,0.635) E34(-17.145,0.635) E35(-18.415,0.635) E36(-19.685,0.635) E37(-20.955,0.635) E38(-22.225,0.635) E39(-23.495,0.635) E40(-24.765,0.635) F1(24.765,-0.635) F2(23.495,-0.635) F3(22.225,-0.635) F4(20.955,-0.635) F5(19.685,-0.635) F6(18.415,-0.635) F7(17.145,-0.635) F8(15.875,-0.635) F9(14.605,-0.635) F10(13.335,-0.635) F11(12.065,-0.635) F12(10.795,-0.635) F13(9.525,-0.635) F14(8.255,-0.635) F15(6.985,-0.635) F16(5.715,-0.635) F17(4.445,-0.635) F18(3.175,-0.635) F19(1.905,-0.635) F20(0.635,-0.635) F21(-0.635,-0.635) F22(-1.905,-0.635) F23(-3.175,-0.635) F24(-4.445,-0.635) F25(-5.715,-0.635) F26(-6.985,-0.635) F27(-8.255,-0.635) F28(-9.525,-0.635) F29(-10.795,-0.635) F30(-12.065,-0.635) F31(-13.335,-0.635) F32(-14.605,-0.635) F33(-15.875,-0.635) F34(-17.145,-0.635) F35(-18.415,-0.635) F36(-19.685,-0.635) F37(-20.955,-0.635) F38(-22.225,-0.635) F39(-23.495,-0.635) F40(-24.765,-0.635) G1(24.765,-1.905) G2(23.495,-1.905) G3(22.225,-1.905) G4(20.955,-1.905) G5(19.685,-1.905) G6(18.415,-1.905) G7(17.145,-1.905) G8(15.875,-1.905) G9(14.605,-1.905) G10(13.335,-1.905) G11(12.065,-1.905) G12(10.795,-1.905) G13(9.525,-1.905) G14(8.255,-1.905) G15(6.985,-1.905) G16(5.715,-1.905) G17(4.445,-1.905) G18(3.175,-1.905) G19(1.905,-1.905) G20(0.635,-1.905) G21(-0.635,-1.905) G22(-1.905,-1.905) G23(-3.175,-1.905) G24(-4.445,-1.905) G25(-5.715,-1.905) G26(-6.985,-1.905) G27(-8.255,-1.905) G28(-9.525,-1.905) G29(-10.795,-1.905) G30(-12.065,-1.905) G31(-13.335,-1.905) G32(-14.605,-1.905) G33(-15.875,-1.905) G34(-17.145,-1.905) G35(-18.415,-1.905) G36(-19.685,-1.905) G37(-20.955,-1.905) G38(-22.225,-1.905) G39(-23.495,-1.905) G40(-24.765,-1.905) H1(24.765,-3.175) H2(23.495,-3.175) H3(22.225,-3.175) H4(20.955,-3.175) H5(19.685,-3.175) H6(18.415,-3.175) H7(17.145,-3.175) H8(15.875,-3.175) H9(14.605,-3.175) H10(13.335,-3.175) H11(12.065,-3.175) H12(10.795,-3.175) H13(9.525,-3.175) H14(8.255,-3.175) H15(6.985,-3.175) H16(5.715,-3.175) H17(4.445,-3.175) H18(3.175,-3.175) H19(1.905,-3.175) H20(0.635,-3.175) H21(-0.635,-3.175) H22(-1.905,-3.175) H23(-3.175,-3.175) H24(-4.445,-3.175) H25(-5.715,-3.175) H26(-6.985,-3.175) H27(-8.255,-3.175) H28(-9.525,-3.175) H29(-10.795,-3.175) H30(-12.065,-3.175) H31(-13.335,-3.175) H32(-14.605,-3.175) H33(-15.875,-3.175) H34(-17.145,-3.175) H35(-18.415,-3.175) H36(-19.685,-3.175) H37(-20.955,-3.175) H38(-22.225,-3.175) H39(-23.495,-3.175) H40(-24.765,-3.175) J1(24.765,-4.445) J2(23.495,-4.445) J3(22.225,-4.445) J4(20.955,-4.445) J5(19.685,-4.445) J6(18.415,-4.445) J7(17.145,-4.445) J8(15.875,-4.445) J9(14.605,-4.445) J10(13.335,-4.445) J11(12.065,-4.445) J12(10.795,-4.445) J13(9.525,-4.445) J14(8.255,-4.445) J15(6.985,-4.445) J16(5.715,-4.445) J17(4.445,-4.445) J18(3.175,-4.445) J19(1.905,-4.445) J20(0.635,-4.445) J21(-0.635,-4.445) J22(-1.905,-4.445) J23(-3.175,-4.445) J24(-4.445,-4.445) J25(-5.715,-4.445) J26(-6.985,-4.445) J27(-8.255,-4.445) J28(-9.525,-4.445) J29(-10.795,-4.445) J30(-12.065,-4.445) J31(-13.335,-4.445) J32(-14.605,-4.445) J33(-15.875,-4.445) J34(-17.145,-4.445) J35(-18.415,-4.445) J36(-19.685,-4.445) J37(-20.955,-4.445) J38(-22.225,-4.445) J39(-23.495,-4.445) J40(-24.765,-4.445) K1(24.765,-5.715) K2(23.495,-5.715) K3(22.225,-5.715) K4(20.955,-5.715) K5(19.685,-5.715) K6(18.415,-5.715) K7(17.145,-5.715) K8(15.875,-5.715) K9(14.605,-5.715) K10(13.335,-5.715) K11(12.065,-5.715) K12(10.795,-5.715) K13(9.525,-5.715) K14(8.255,-5.715) K15(6.985,-5.715) K16(5.715,-5.715) K17(4.445,-5.715) K18(3.175,-5.715) K19(1.905,-5.715) K20(0.635,-5.715) K21(-0.635,-5.715) K22(-1.905,-5.715) K23(-3.175,-5.715) K24(-4.445,-5.715) K25(-5.715,-5.715) K26(-6.985,-5.715) K27(-8.255,-5.715) K28(-9.525,-5.715) K29(-10.795,-5.715) K30(-12.065,-5.715) K31(-13.335,-5.715) K32(-14.605,-5.715) K33(-15.875,-5.715) K34(-17.145,-5.715) K35(-18.415,-5.715) K36(-19.685,-5.715) K37(-20.955,-5.715) K38(-22.225,-5.715) K39(-23.495,-5.715) K40(-24.765,-5.715)
